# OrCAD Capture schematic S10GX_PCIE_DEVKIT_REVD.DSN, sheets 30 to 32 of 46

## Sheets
30 Max10 USB Blaster II: size C
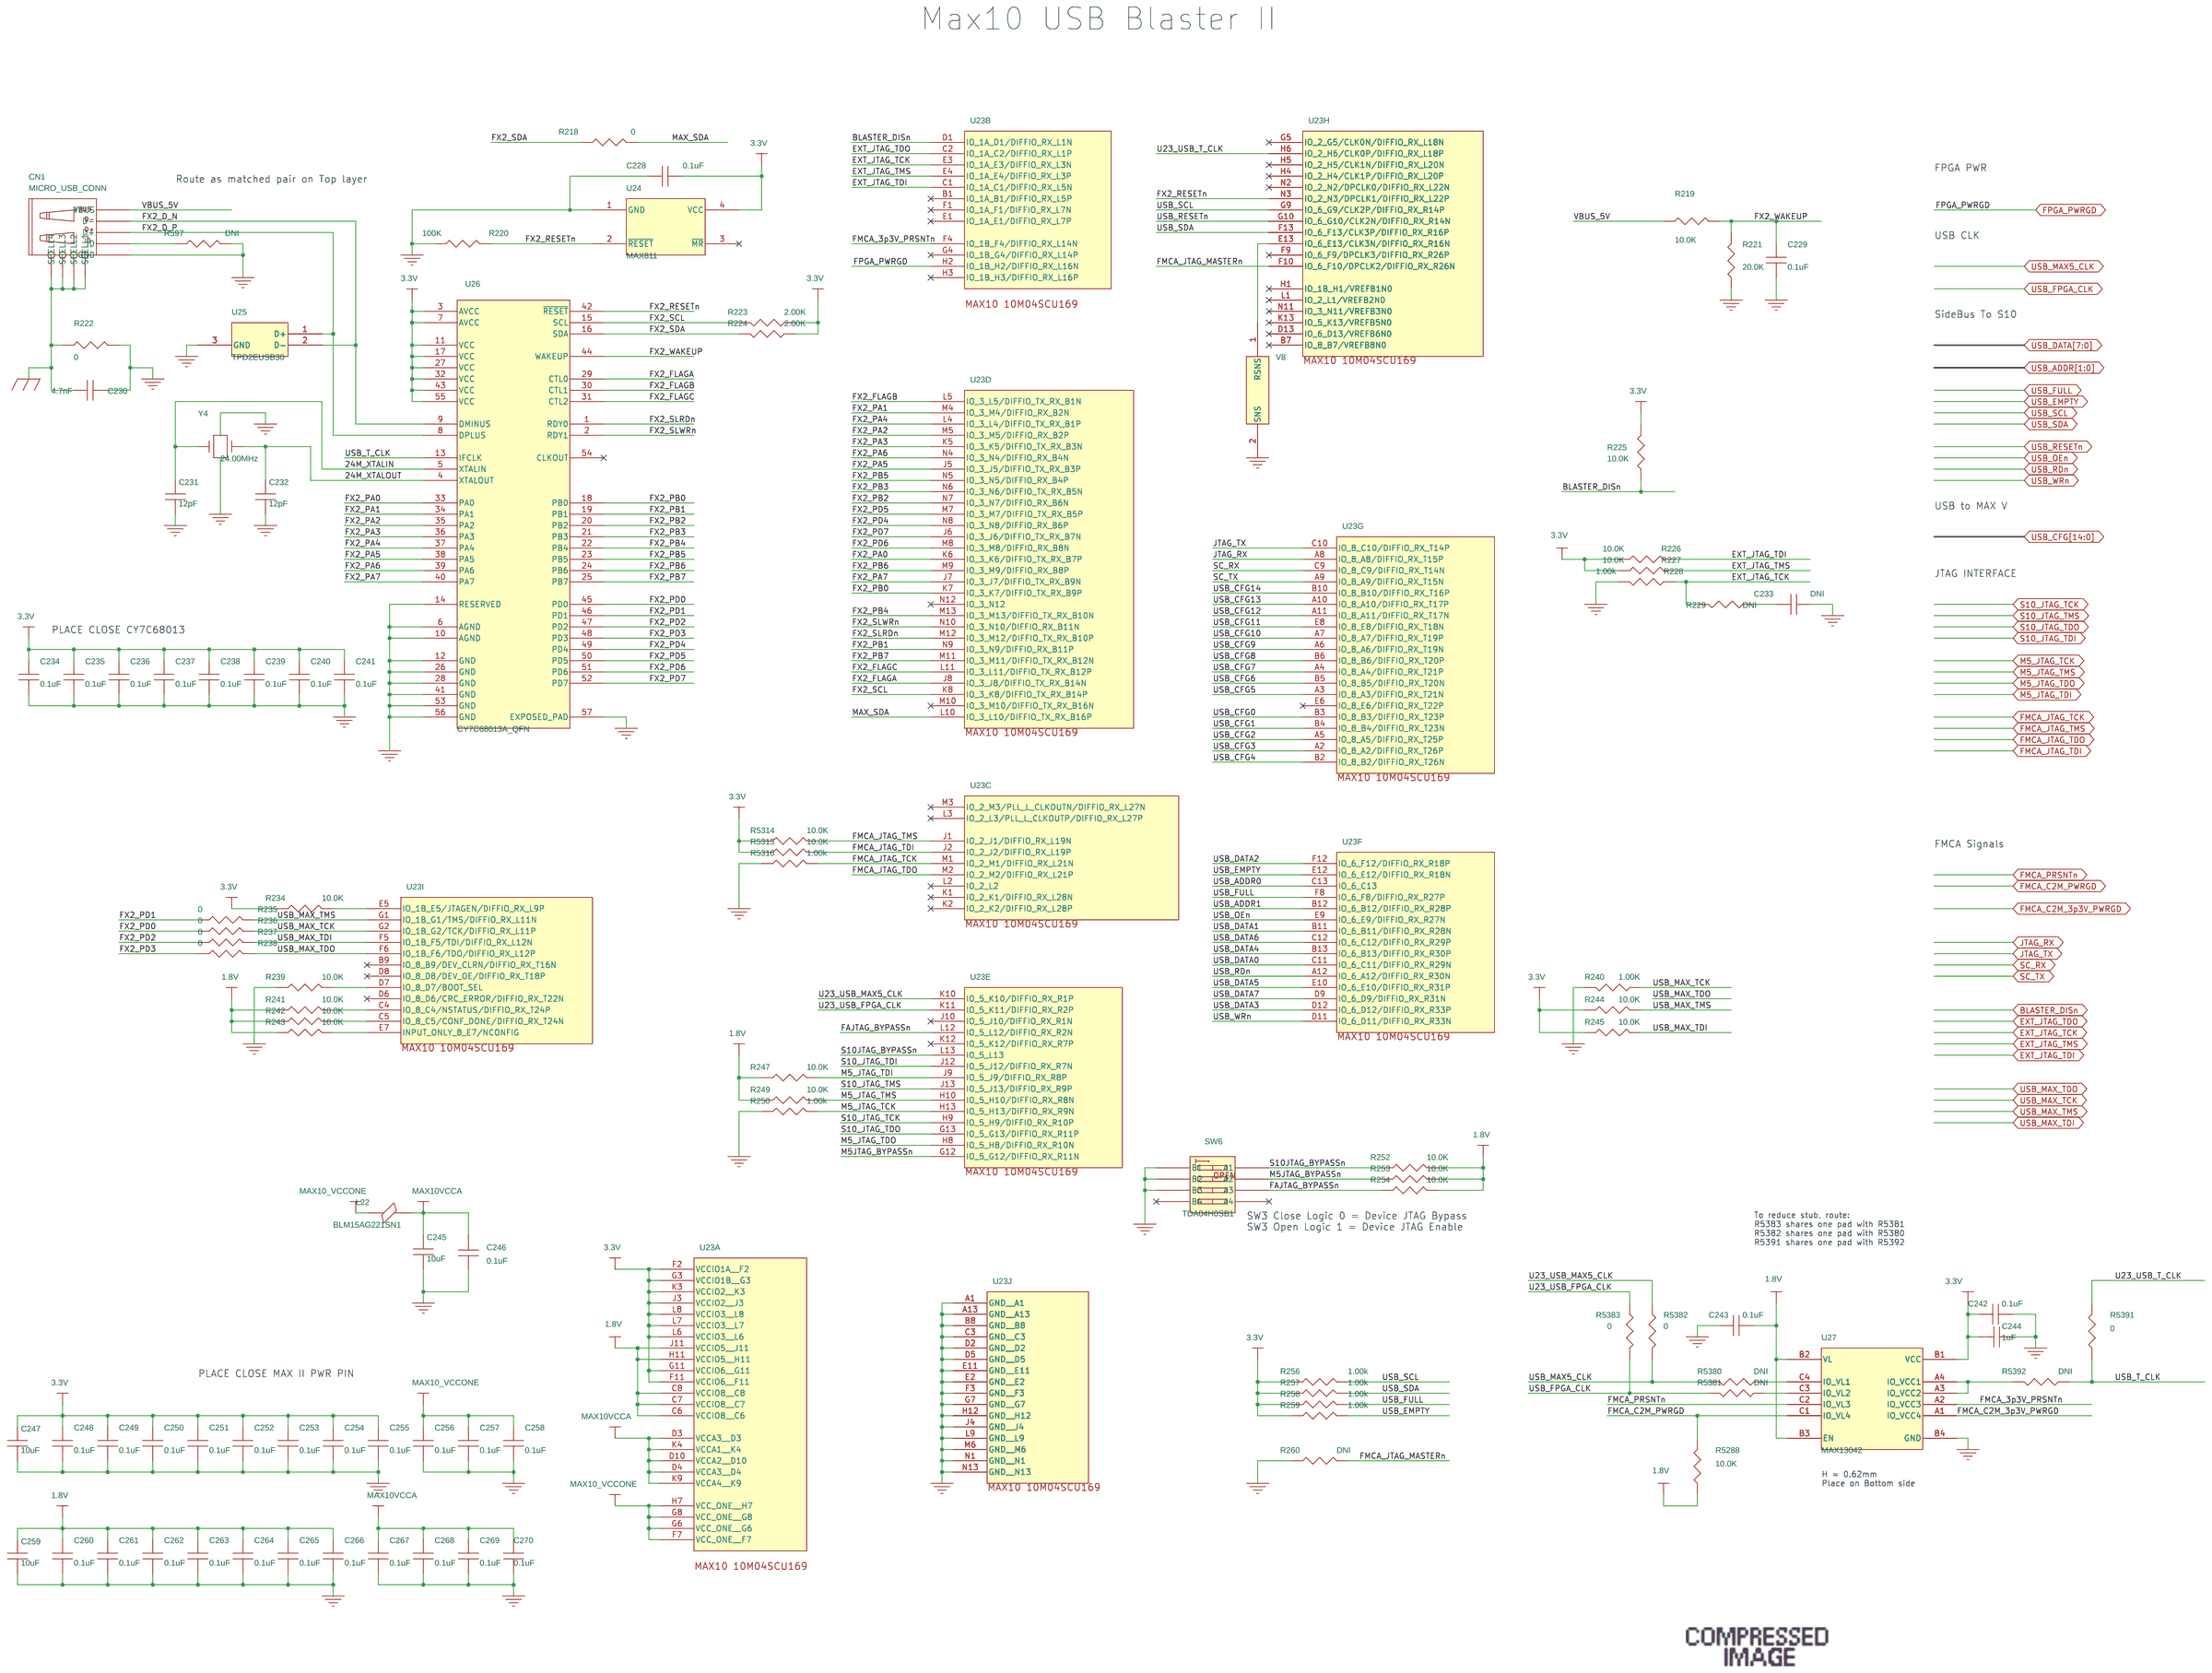
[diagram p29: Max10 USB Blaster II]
31 LT2987 Power Seq: size C
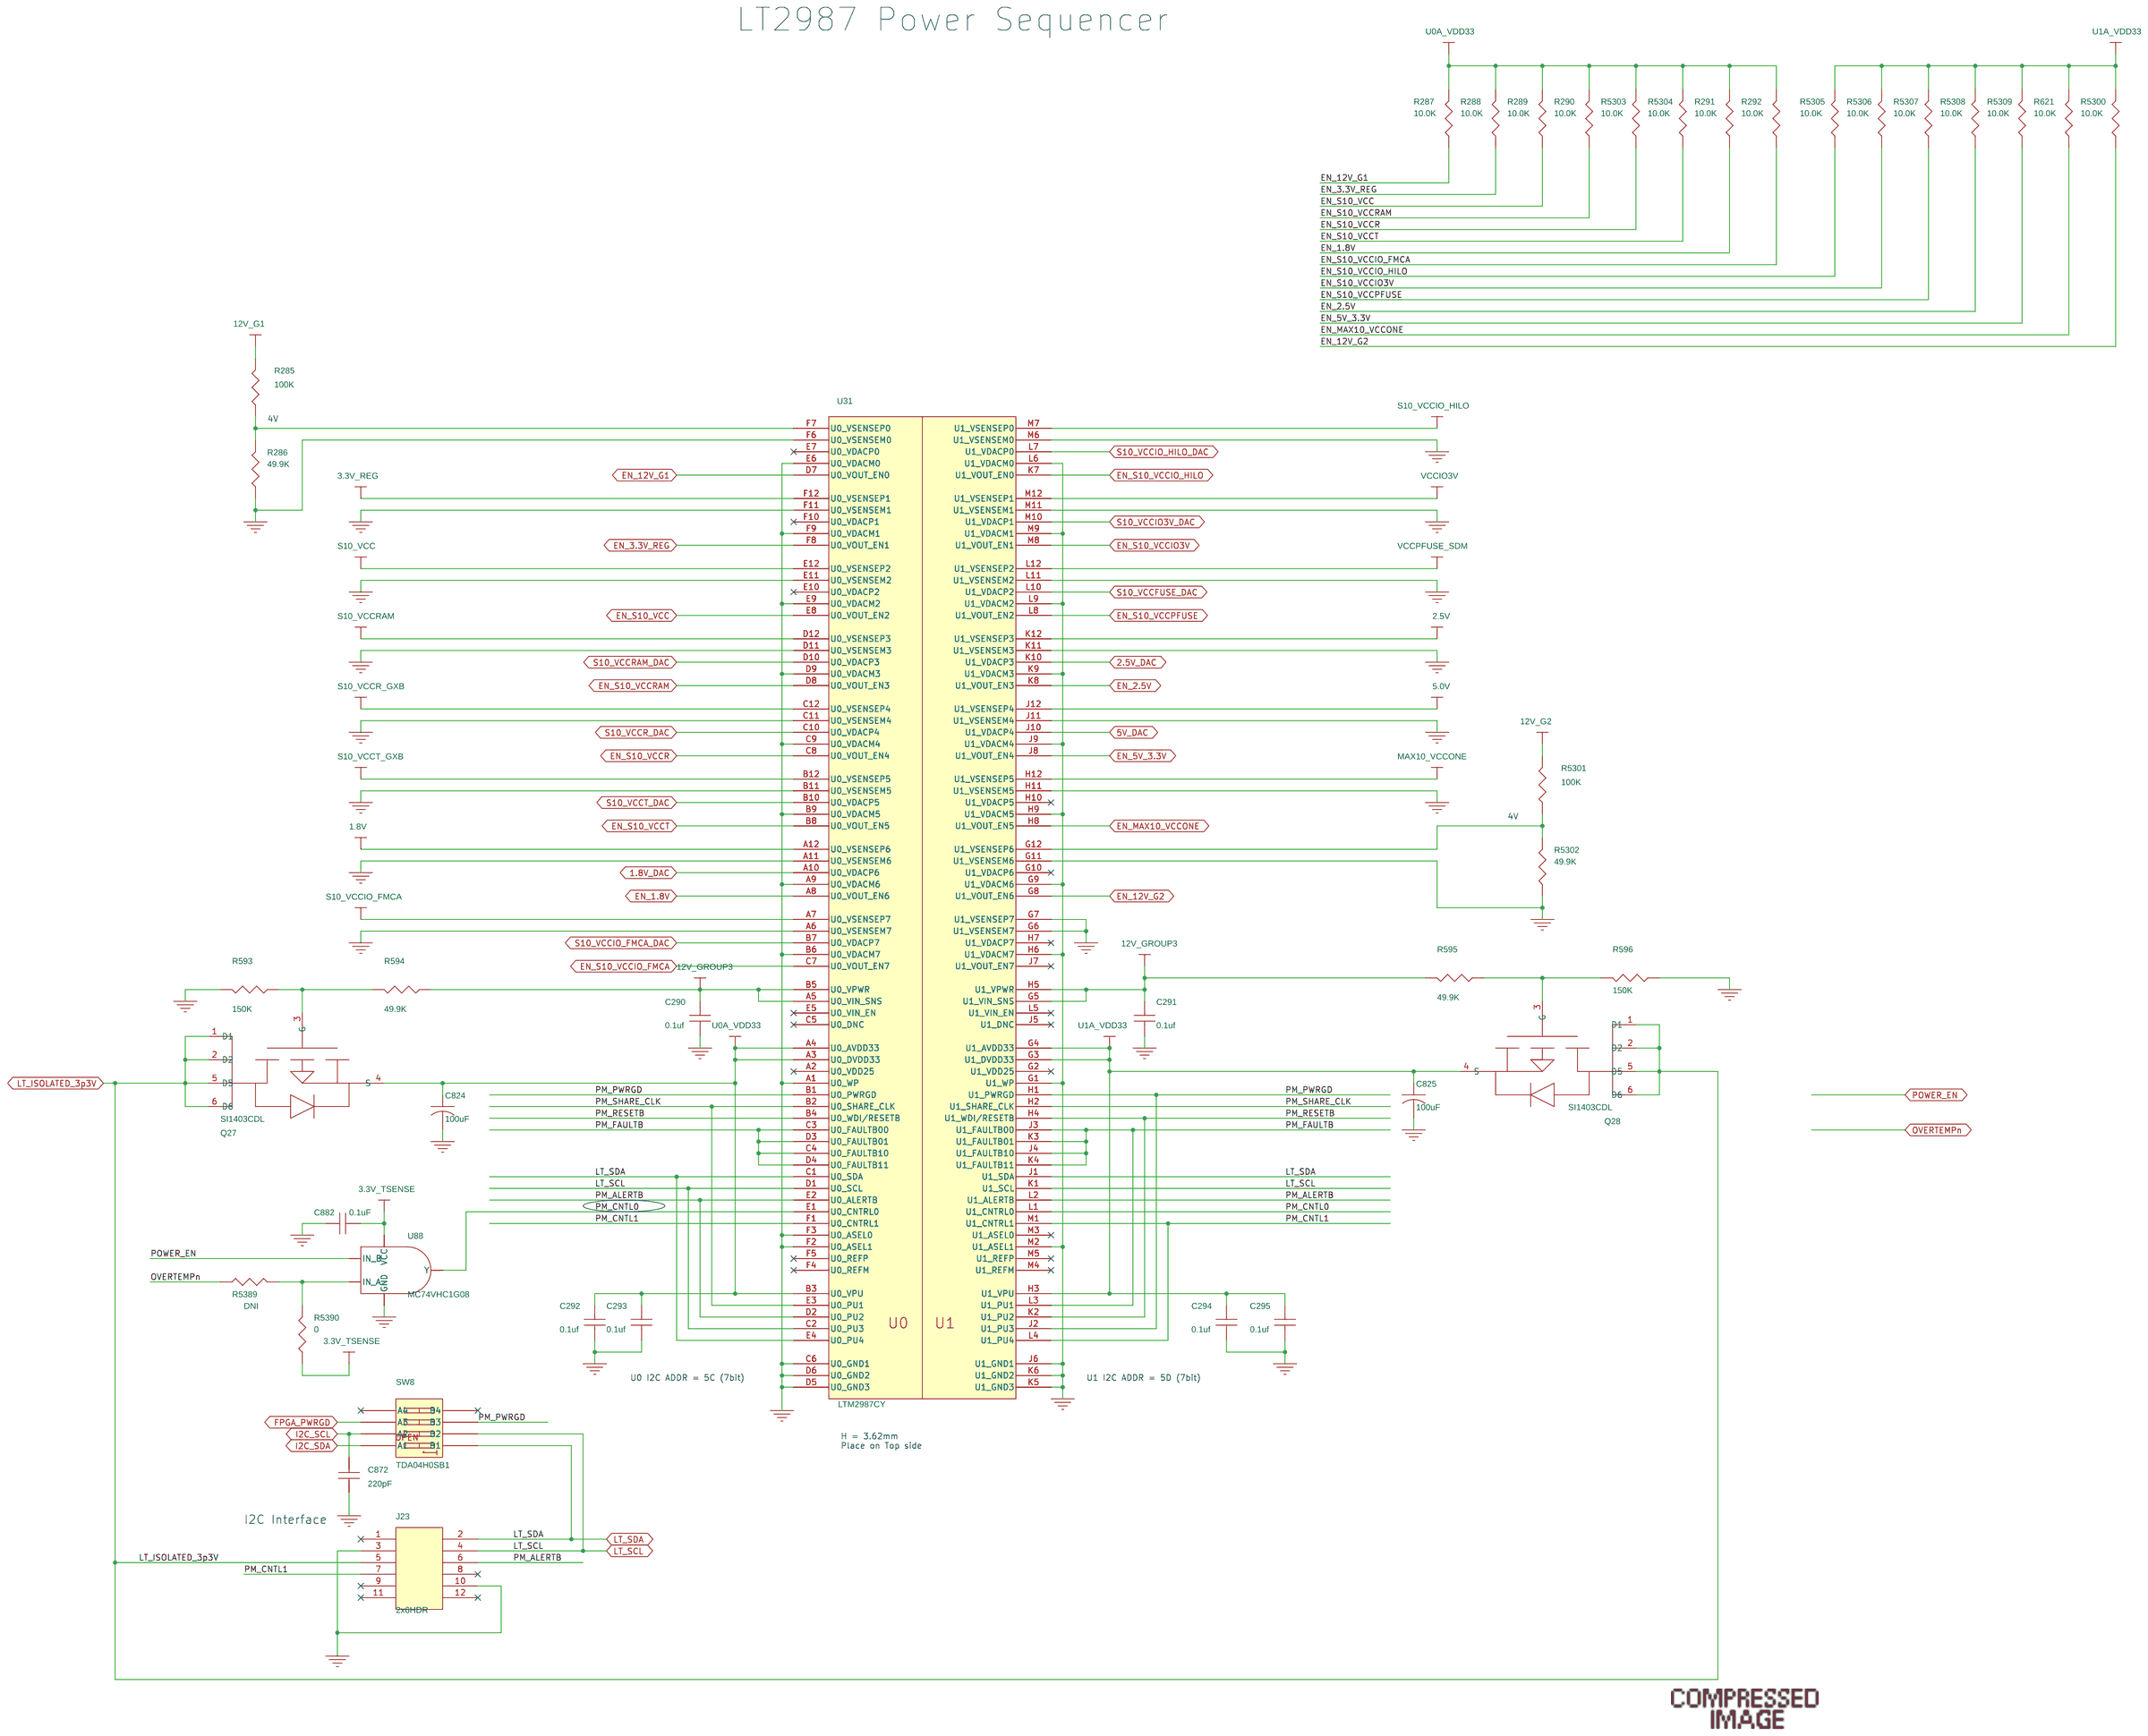
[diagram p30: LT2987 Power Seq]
32 Current & Temp Sense: size C
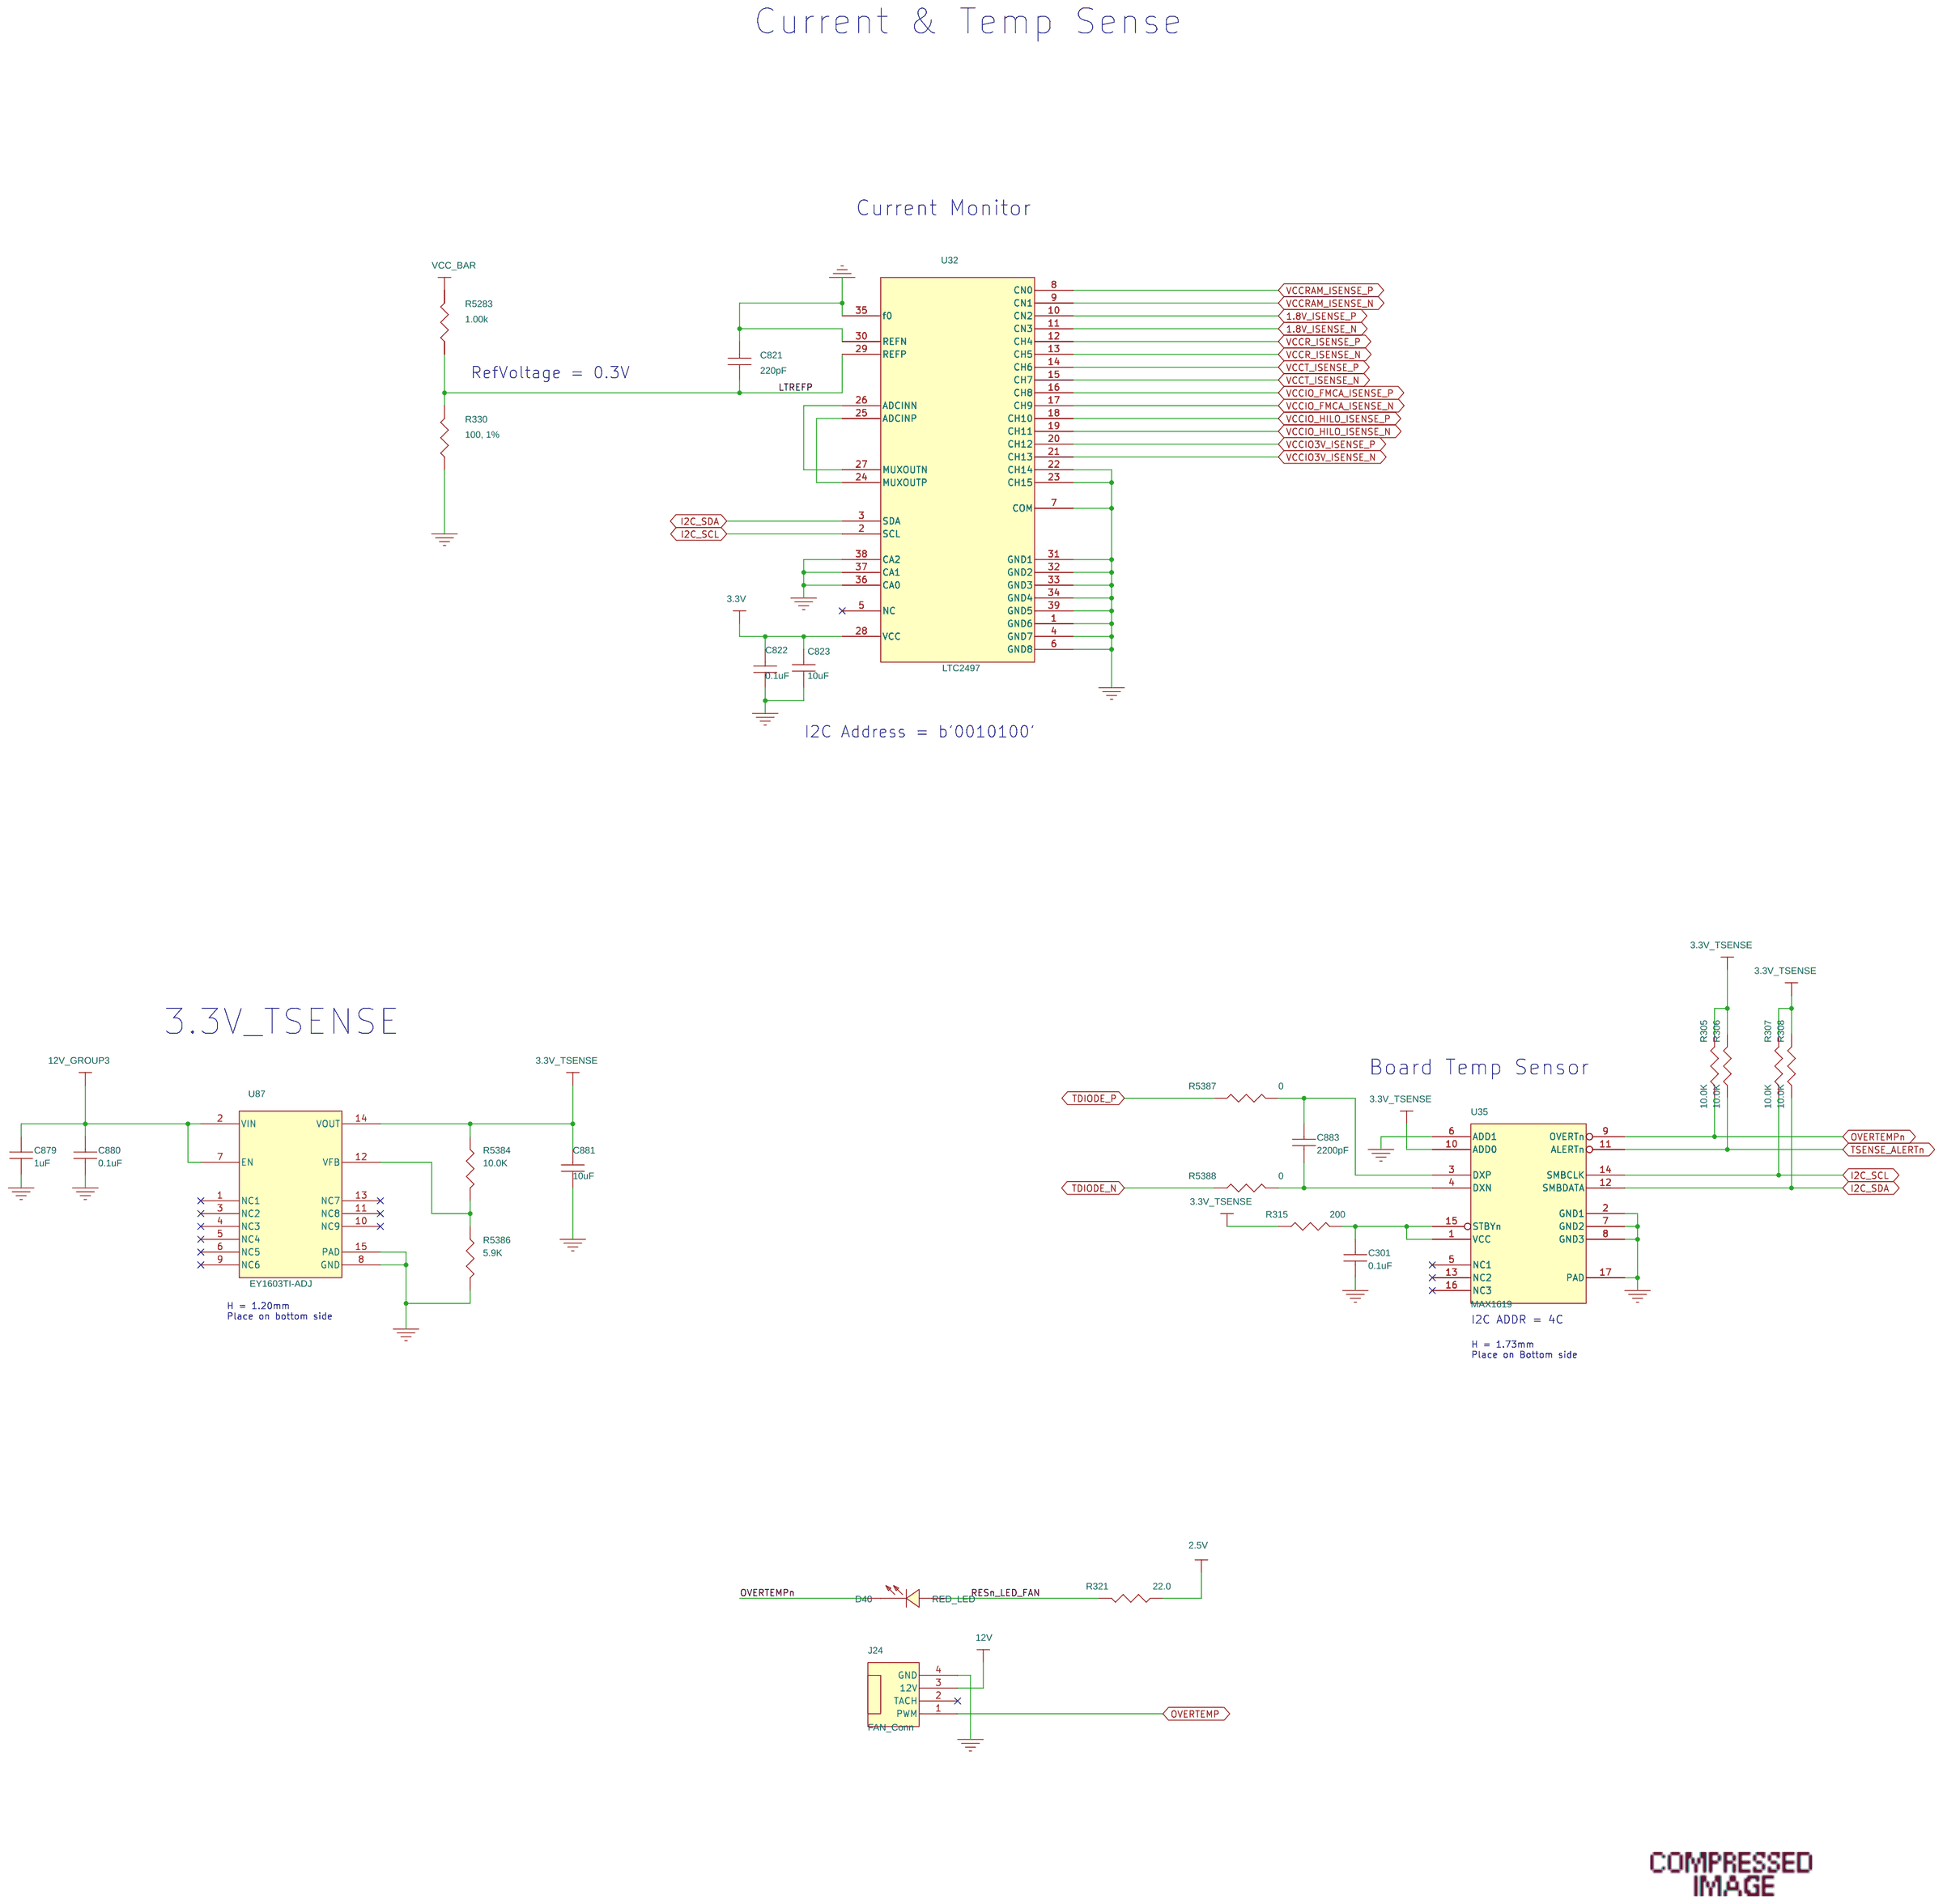
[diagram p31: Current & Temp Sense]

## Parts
sheet Current & Temp Sense
C301  0.1uF  [0402]
C821  220pF  [0402]
C822  0.1uF  [0402]
C823  10uF  [C0805]
C879  1uF  [0603]
C880  0.1uF  [0402]
C881  10uF  [0603]
C883  2200pF  [0402]
D40  RED_LED  [LED_0603]
J24  FAN_Conn  [Molex_0470533000]
R305  10.0K  [0402]
R306  10.0K  [0402]
R307  10.0K  [0402]
R308  10.0K  [0402]
R315  200  [0402]
R321  22.0  [0402]
R330  100, 1%  [0402]
R5283  1.00k  [0402]
R5384  10.0K  [0402]
R5386  5.9K  [0402]
R5387  0  [0402]
R5388  0  [0402]
U32  LTC2497  [LTQFN38]
U35  MAX1619  [QSOP16_EP]
U87  EY1603TI-ADJ  [HTSSOP-14]
sheet LT2987 Power Seq
C290  0.1uf  [0603]
C291  0.1uf  [0603]
C292  0.1uf  [0603]
C293  0.1uf  [0603]
C294  0.1uf  [0603]
C295  0.1uf  [0603]
C824  100uF  [Avx-1210_case-b]
C825  100uF  [Avx-1210_case-b]
C872  220pF  [0402]
C882  0.1uF  [0402]
J23  2x6HDR  [2X6HDR-2mmX2mm]
Q27  SI1403CDL  [SOT-363]
Q28  SI1403CDL  [SOT-363]
R285  100K  [0402]
R286  49.9K  [0402]
R287  10.0K  [0402]
R288  10.0K  [0402]
R289  10.0K  [0402]
R290  10.0K  [0402]
R291  10.0K  [0402]
R292  10.0K  [0402]
R593  150K  [0402]
R594  49.9K  [0402]
R595  49.9K  [0402]
R596  150K  [0402]
R621  10.0K  [0402]
R5300  10.0K  [0402]
R5301  100K  [0402]
R5302  49.9K  [0402]
R5303  10.0K  [0402]
R5304  10.0K  [0402]
R5305  10.0K  [0402]
R5306  10.0K  [0402]
R5307  10.0K  [0402]
R5308  10.0K  [0402]
R5309  10.0K  [0402]
R5389  DNI  [0402]
R5390  0  [0402]
SW8  TDA04H0SB1  [DIPSWITCH_SMT_QUAD]
U31  LTM2987CY  [BGA-144]
U88  MC74VHC1G08  [TSOP-5]
sheet Max10 USB Blaster II
C228  0.1uF  [0402]
C229  0.1uF  [0402]
C230  4.7nF  [0402]
C231  12pF  [0402]
C232  12pF  [0402]
C233  DNI  [0402]
C234  0.1uF  [0402]
C235  0.1uF  [0402]
C236  0.1uF  [0402]
C237  0.1uF  [0402]
C238  0.1uF  [0402]
C239  0.1uF  [0402]
C240  0.1uF  [0402]
C241  0.1uF  [0402]
C242  0.1uF  [0402]
C243  0.1uF  [0402]
C244  1uF  [0402]
C245  10uF  [0603]
C246  0.1uF  [0402]
C247  10uF  [0603]
C248  0.1uF  [0402]
C249  0.1uF  [0402]
C250  0.1uF  [0402]
C251  0.1uF  [0402]
C252  0.1uF  [0402]
C253  0.1uF  [0402]
C254  0.1uF  [0402]
C255  0.1uF  [0402]
C256  0.1uF  [0402]
C257  0.1uF  [0402]
C258  0.1uF  [0402]
C259  10uF  [0603]
C260  0.1uF  [0402]
C261  0.1uF  [0402]
C262  0.1uF  [0402]
C263  0.1uF  [0402]
C264  0.1uF  [0402]
C265  0.1uF  [0402]
C266  0.1uF  [0402]
C267  0.1uF  [0402]
C268  0.1uF  [0402]
C269  0.1uF  [0402]
C270  0.1uF  [0402]
CN1  MICRO_USB_CONN  [molex-micro-usb-47589-001]
L22  BLM15AG221SN1  [0402]
R218  0  [0402]
R219  10.0K  [0402]
R220  100K  [0402]
R221  20.0K  [0402]
R222  0  [0402]
R223  2.00K  [0402]
R224  2.00K  [0402]
R225  10.0K  [0402]
R226  10.0K  [0402]
R227  10.0K  [0402]
R228  1.00k  [0402]
R229  DNI  [0402]
R234  10.0K  [0402]
R235  0  [0402]
R236  0  [0402]
R237  0  [0402]
R238  0  [0402]
R239  10.0K  [0402]
R240  1.00K  [0402]
R241  10.0K  [0402]
R242  10.0K  [0402]
R243  10.0K  [0402]
R244  10.0K  [0402]
R245  10.0K  [0402]
R247  10.0K  [0402]
R249  10.0K  [0402]
R250  1.00k  [0402]
R252  10.0K  [0402]
R253  10.0K  [0402]
R254  10.0K  [0402]
R256  1.00k  [0402]
R257  1.00k  [0402]
R258  1.00k  [0402]
R259  1.00k  [0402]
R260  DNI  [0402]
R597  DNI  [0402]
R5288  10.0K  [0402]
R5314  10.0K  [0402]
R5315  10.0K  [0402]
R5316  1.00k  [0402]
R5380  DNI  [0402]
R5381  DNI  [0402]
R5382  0  [0402]
R5383  0  [0402]
R5391  0  [0402]
R5392  DNI  [0402]
SW6  TDA04H0SB1  [DIPSWITCH_SMT_QUAD]
U23  10M04SCU169  [BGA169-0R80-11X11]  (sections A,B,C,D,E,F,G,H,I,J)
U24  MAX811  [SOT-143]
U25  TPD2EUSB30  [DRT]
U26  CY7C68013A_QFN  [QFN56]
U27  MAX13042  [UCSP-12]
V8  SENSE_PAD  [SENSE]
Y4  24.00MHz  [XTAL_FA-128]

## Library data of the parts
C301 C880 C882 = CAP: CAP - CERAMIC,  0.1UF 0402 25VDC Y5V; AGILE_LINK: http://sj-agile9app/Agile/PLMServlet?action=OpenEmailObject&classid=10000&objid=213459527; Item Num: P03-15057R; LIFECYCLE_PHASE: Active; Lead Free Status: Lead Free; MFR_LIFECYCLE: Active; Manufacturer: Murata; Manufacturer Part Num: GRM155F51E104ZA01D; Num Pins: 2; PART_SUBCLASS: CAPACITORS; Part Class: CAPACITORS; RATED_VOLTAGE: 25V; RoHS Compliant: RoHS Compliant; TOLERANCE: +80%/-20%
C821 C872 = CAP: CAP - CERAMIC, 220PF, 10%, 50V, 0402, X7R; Dielectric: X5R; Item Num: P03-15090R; Lead Free Status: Yes; Manufacturer: Murata; Manufacturer Part Num: GRM155R71H221KA01D; Manufacturer's Part No.: GRM155R71H221KA01D; Num Pins: 2; Part Class: CAPACITORS; Price: 0.07; RoHS Compliant: Yes; Tolerance: 10%
C822 = CAP: CAP CER 0.1UF 25V 20% X7R 0402; Item Num: P03-17618R; LIFECYCLE_PHASE: Active; Lead Free Status: Lead Free; Manufacturer: Murata; Manufacturer Part Num: GRM155R71E104KE14D; Num Pins: 2; Part Class: CAPACITORS; Price: 0; RoHS Compliant: RoHS Compliant
C823 = CAP: SMD/SMT 10uF 10% 16Volts  0805; Item Num: P03-17702R; Lead Free Status: No; Manufacturer: TDK Electronics; Manufacturer Part Num: C2012X5R1C106K085AC; Manufacturer's Part No.: ECJ-2FB1A106K; Num Pins: 2; Part Class: CAPACITORS; RoHS Compliant: Yes
C879 = CAP: CAP - CER, 1UF, 25V, +/-10%, X5R, 0603 SMD; AGILE_LINK: http://sj-agile9app/Agile/PLMServlet?action=OpenEmailObject&classid=10000&objid=213459527; Item Num: P03-16324R; LIFECYCLE_PHASE: Active; Lead Free Status: Lead Free; MFR_LIFECYCLE: Active; Manufacturer: Murata; Manufacturer Part Num: GRM188R61E105KA12D; Num Pins: 2; PART_SUBCLASS: CAPACITORS; Part Class: CAPACITORS; RATED_VOLTAGE: 25V; RoHS Compliant: RoHS Compliant; TOLERANCE: +/-10%
C881 = CAP: CAP CER 10UF 25V 20% JB 0603; Item Num: P03-17784R; Lead Free Status: Yes; Manufacturer: TDK; Manufacturer Part Num: C1608JB1E106M080AC; Num Pins: 2; Part Class: Capacitors; Price: 0; RoHS Compliant: Yes
C883 = CAP: CCAP CER 2200PF 50V 10% X7R 0402; AGILE_LINK: http://sj-agile9app/Agile/PLMServlet?action=OpenEmailObject&classid=10000&objid=213459527; Item Num: P03-15048R; LIFECYCLE_PHASE: Active; Lead Free Status: Lead Free; MFR_LIFECYCLE: Active; Manufacturer: Murata; Manufacturer Part Num: GRM155R71H222KA01D; Num Pins: 2; PART_SUBCLASS: CAPACITORS; Part Class: CAPACITORS; RATED_VOLTAGE: 50V; RoHS Compliant: RoHS Compliant; TOLERANCE: +80%/-20%
D40 = LED_WURTH: LED -SUPER RED, VF=1.9V, IF=0.03A, 0603; Item Num: P09-21345R; LIFECYCLE_PHASE: Active; Lead Free Status: Lead Free; Manufacturer: Wurth Electroniks; Manufacturer Part Num: 150060SS75000; Num Pins: 2; PART_SUBCLASS: LEDS; Part Class: LEDS; RoHS Compliant: RoHS Compliant
J24 = FAN_Conn: 4 POSITIONS HEADER, UNSHROUDED CONNECTOR 0.100" (2.54MM) THROUGH HOLE TIN; Item Num: P23-38775R; Manufacturer Name: Molex; Manufacturer Part Num: 0470533000
R226 R227 R234 R239 R241-R245 R247 R249 R252-R254 R305-R308 R5288 R5314 R5315 = RESISTOR: RES,10.0K OHMS,1.0%,1/16W, 0402; AGILE_LINK: http://sj-agile9app/Agile/PLMServlet?action=OpenEmailObject&classid=10000&objid=146548997; Item Num: P02-11364R; LIFECYCLE_PHASE: Active; Lead Free Status: No; MFR_LIFECYCLE: Active; Manufacturer: Panasonic; Manufacturer Part Num: ERJ-2RKF1002X; Num Pins: 2; PART_SUBCLASS: RESISTORS; POWER: 1/16W; RoHS Compliant: Yes; TOLERANCE: +/-1%
R315 = RESISTOR: RES 200 OHM 1/16W 5% 0402 SMD; Item Num: P02-14026R; Manufacturer: Panasonic; Manufacturer Part Num: ERJ-2GEJ201X; Num Pins: 2; Part Class: RESISTORS; RoHS Compliant: Yes
R321 = RESISTOR: RES - 22.0 OHM, 1/16W, 1%, 0402 SMD; Item Num: P02-16269R; Lead Free Status: Yes; Manufacturer: Panasonic; Manufacturer Part Num: ERJ-2RKF22R0X; Num Pins: 2; Part Class: Resistors; Price: 0
R330 = RESISTOR: RES,100 OHMS,1.0%,1/16W,0402; Item Num: P02-11381R; Lead Free Status: No; Manufacturer: Panasonic; Manufacturer Part Num: ERJ-2RKF1000X; Num Pins: 2; Part Class: Resistors; Price: 0; RoHS Compliant: Yes; Tolerance: 1%
R228 R250 R256-R259 R5283 R5316 = RESISTOR: RES,1.00K OHMS,1.0%,1/16W,0402; Item Num: P02-11372R; Lead Free Status: No; Manufacturer: Panasonic; Manufacturer Part Num: ERJ-2RKF1001X; Num Pins: 2; Part Class: Resistors
R219 R287-R292 R621 R5300 R5303-R5309 R5384 = RESISTOR: RES,10.0K OHMS,1.0%,1/16W, 0402; AGILE_LINK: http://sj-agile9app/Agile/PLMServlet?action=OpenEmailObject&classid=10000&objid=146548997; Item Num: P02-11364R; LIFECYCLE_PHASE: Active; Lead Free Status: No; MFR_LIFECYCLE: Active; Manufacturer: Panasonic; Manufacturer Part Num: ERJ-2RKF1002X; Num Pins: 2; PART_SUBCLASS: RESISTORS; POWER: 1/16W; RESISTANCE: 10K; RoHS Compliant: Yes; TOLERANCE: +/-1%
R5386 = RESISTOR: RES - 5.9K OHM, 1/16W, 1%, 0402 SMD; AGILE_LINK: http://sj-agile9app/Agile/PLMServlet?action=OpenEmailObject&classid=10000&objid=146548997; Item Num: P02-15347R; LIFECYCLE_PHASE: Active; Lead Free Status: No; MFR_LIFECYCLE: Active; Manufacturer: Panasonic; Manufacturer Part Num: ERJ-2RKF5901x; Num Pins: 2; PART_SUBCLASS: RESISTORS; POWER: 1/16W; RoHS Compliant: Yes; TOLERANCE: +/-1%
R218 R222 R235-R238 R5382 R5383 R5387 R5388 R5390 R5391 = RESISTOR: RES ZERO OHM 1/16W 5% 0402 SMD; Altera Part No.: P02-14020R; Item Num: P02-14020R; Lead Free Status: No; Manufacturer: Panasonic; Manufacturer Part Num: ERJ-2GE0R00X; Num Pins: 2; Part Class: RESISTORS; RoHS Compliant: Yes; Tolerance: 5%
U32 = LTC2497
U35 = MAX1619_0: IC, Temperature Sensor, SMBus Interface, QSOP-16; AGILE_LINK: http://sj-agile9app/Agile/PLMServlet?action=OpenEmailObject&classid=10000&objid=188479272; Item Num: P01-13019R; LIFECYCLE_PHASE: Active; Lead Free Status: Lead Free; MFR_LIFECYCLE: Active; Manufacturer: Maxim Integrated Products, Inc.; Manufacturer Part Num: MAX1619MEE+T; Num Pins: 16; PART_SUBCLASS: ICS; Price: 3.5; RoHS Compliant: RoHS Compliant
U87 = EY1603TI-ADJ: IC - EY1603 40V, LOW QUIESCENT CURRENT, 150MA LINEAR REGULATOR; Item Num: P01-18060R; Manufacturer: Altera
C290-C295 = CAP: CAP - 0.1UF 0603 16V X7R; AGILE_LINK: http://sj-agile9app/Agile/PLMServlet?action=OpenEmailObject&classid=10000&objid=14603414; CAPACITANCE: 0.1uF; Item Num: P03-08618R; LIFECYCLE_PHASE: Active; MFR_LIFECYCLE: Active; Manufacturer: Murata; Manufacturer Part Num: GRM188R71C104KA01D; Num Pins: 2; PART_SUBCLASS: CAPACITORS; Price: 0.154; RATED_VOLTAGE: 16V; RoHS Compliant: RoHS Compliant; Supplier Part Num: PCC1762TR-ND
C824 C825 = PCAP: CAP - TANT, 100UF, 6.3V, 20%, ESR 0.045 OHM, POLY SMD; AGILE_LINK: http://sj-agile9app/Agile/PLMServlet?action=OpenEmailObject&classid=10000&objid=257237054; Item Num: P03-17352R; LIFECYCLE_PHASE: Active; Lead Free Status: Lead Free; MFR_LIFECYCLE: Active; Manufacturer: AVX Corp; Manufacturer Part Num: TCJB107M006R0045; Num Pins: 2; PART_SUBCLASS: CAPACITORS; RATED_VOLTAGE: 6.3V; RoHS Compliant: RoHS Compliant; TOLERANCE: +/-20%
J23 = 2X6HDR: CONN HEADER 12POS 2MM SMT DL PCB; Item Num: P23-38256R; Manufacturer Part Num: 98424-G52-12LF
Q27 Q28 = SI1403DL: MOSFET P-CH 20V 1.6A SOT-363; Item Num: P18-31470R; Manufacturer: Vishay Siliconix; Manufacturer Part Num: SI1403CDL-T1-GE3
R220 R285 R5301 = RESISTOR: RES,100K OHMS,1.0%,1/16W,0402; Item Num: P02-11386R; Lead Free Status: No; Manufacturer: Panasonic; Manufacturer Part Num: ERJ-2RKF1003X; Num Pins: 2; Part Class: Resistors; Price: 0; RoHS Compliant: Yes
R286 R594 R595 R5302 = RESISTOR: RES 49.9K OHM 1/16W 1% 0402 SMD; Item Num: P02-15867R; Lead Free Status: Yes; Manufacturer: Panasonic; Manufacturer Part Num: ERJ-2RKF4992X; Num Pins: 2; Part Class: Resistors; Price: 0
R593 R596 = RESISTOR: RES - 150K OHMS, 1.0%, 1/16W, 0402; Item Num: P02-15627R; Lead Free Status: Yes; Manufacturer: Panasonic; Manufacturer Part Num: ERJ-2RKF1503x; Num Pins: 2; Part Class: Resistors; Price: 0
R597 R5389 = RESISTOR: RES ZERO OHM 1/16W 5% 0402 SMD; Altera Part No.: P02-14020R; Item Num: P02-14020R; Lead Free Status: No; Manufacturer: Panasonic; Manufacturer Part Num: ERJ-2GE0R00X; Num Pins: 2; Part Class: RESISTORS; Price: 0; RoHS Compliant: Yes; Tolerance: 5%
SW8 = SPST4: SWITCHES - 4 POS, 8 PIN, Ultra-mini SMT Half-pitch Slider DIP Switch; AGILE_LINK: http://sj-agile9app/Agile/PLMServlet?action=OpenEmailObject&classid=10000&objid=258073635; Item Num: P11-24098R; LIFECYCLE_PHASE: Preliminary; Lead Free Status: Not Lead Free; MFR_LIFECYCLE: Active; Manufacturer: C & K Components/ITT Industries; Num Pins: 8; PART_SUBCLASS: SWITCHES; RoHS Compliant: RoHS Compliant
U31 = LT2987CY_0: IC 16-CHL UMODULE PMBUS PWR SYS MANAGER LTM2987; Item Num: P01-18011R; Manufacturer: Linear Technology; Manufacturer Part Num: LTM2987CY#PBF; Manufacturer Part Number: LTM2987CY#PBF
U88 = Single_2-input_AND-Gate: IC GATE AND SGL CMOS 2IN 5TSOP; Item Num: P01-17902R; Manufacturer: On-Semi; Manufacturer Part Num: MC74VHC1G08DTT1G
C228 C229 C234-C241 C248-C258 C260-C270 = CAP: CAP - CERAMIC,  0.1UF 0402 25VDC Y5V; Dielectric: Y5V; Item Num: P03-15057R; LIFECYCLE_PHASE: Active; Lead Free Status: Lead Free; MFR_LIFECYCLE: Active; Manufacturer: Murata; Manufacturer Part Num: GRM155F51E104ZA01D; Num Pins: 2; PART_SUBCLASS: CAPACITORS; Part Class: CAPACITORS; RATED_VOLTAGE: 25V; RoHS Compliant: RoHS Compliant; TOLERANCE: +80%/-20%
C230 = CAP: CAP - CER 4700PF 50V 10% X7R 0402; AGILE_LINK: http://sj-agile9app/Agile/PLMServlet?action=OpenEmailObject&classid=10000&objid=215384813; Item Num: P03-15074R; LIFECYCLE_PHASE: Active; Lead Free Status: Lead Free; MFR_LIFECYCLE: Active; Manufacturer: Murata; Manufacturer Part Num: GRM155R71H472KA01D; Num Pins: 2; PACKAGING: Tape & Reel (TR); PART_SUBCLASS: CAPACITORS; RATED_VOLTAGE: 50V; RoHS Compliant: RoHS Compliant; Supplier Part Num: GRM155R71H472KA01D; Tolerance: +/-10%
C231 C232 = CAP: CAP - 12PF, 50V, +/-5%, CERAMIC, 0402 SMD; AGILE_LINK: http://sj-agile9app/Agile/PLMServlet?action=OpenEmailObject&classid=10000&objid=257385742; Item Num: P03-15352R; LIFECYCLE_PHASE: Active; Lead Free Status: Lead Free; MFR_LIFECYCLE: Active; Manufacturer: Murata; Manufacturer Part Num: GRM1555C1H120JA01D; Num Pins: 2; PART_SUBCLASS: CAPACITORS; RATED_VOLTAGE: 50V; RoHS Compliant: RoHS Compliant; TOLERANCE: +/-5%
C233 = CAP: CAP DNI 0402; LIFECYCLE_PHASE: Active; Lead Free Status: Lead Free; Num Pins: 2; Part Class: CAPACITORS; Price: 0
C242 C243 C246 = CAP_NP: CAP, CERAMIC, 0.1UF, 0402, 10%, 10VDC,  X5R; AGILE_LINK: http://sj-agile9app/Agile/PLMServlet?action=OpenEmailObject&classid=10000&objid=188516424; Item Num: P03-15030R; LIFECYCLE_PHASE: Active; MFR_LIFECYCLE: Active; Manufacturer: Murata; Manufacturer Part Num: GRM155R61A104KA01D; Num Pins: 2; PART_SUBCLASS: CAPACITORS; RATED_VOLTAGE: 10V; RoHS Compliant: RoHS Compliant; TOLERANCE: +/-10%
C244 = CAP: CAP - CER, 1uF, 10V, +/-10%, X5R, 0402; Item Num: P03-15479R; Lead Free Status: Yes; Manufacturer: Murata; Manufacturer Part Num: GRM155R61A105KE15D; Num Pins: 2; Part Class: CAPACITORS; RoHS Compliant: Yes
C245 C247 C259 = CAP: CAP - CER, 10UF, 6.3V, +/-20%, X5R, 0603 SMD; AGILE_LINK: http://sj-agile9app/Agile/PLMServlet?action=OpenEmailObject&classid=10000&objid=260383822; Item Num: P03-16323R; LIFECYCLE_PHASE: Active; Lead Free Status: Lead Free; MFR_LIFECYCLE: Active; Manufacturer: Murata; Manufacturer Part Num: GRM188R60J106ME47D; Num Pins: 2; PART_SUBCLASS: CAPACITORS; RATED_VOLTAGE: 6.3V; RoHS Compliant: RoHS Compliant; TOLERANCE: +/-20%
CN1 = MICRO_USB_CONN: RECEPTACLE, USB 3.0, MICRO B, R/A; Item Num: P23-38552R; Lead Free Status: Yes; MFR_LIFECYCLE: Active; Manufacturer: Molex; Manufacturer Part Num: 47589-0001; Num Pins: 9; Part Class: Connectors; RoHS Compliant: Yes
L22 = BEAD_FERRITE_SM: IND - SMD EMI FILTERS/CHIP FERRITE BEAD, 220-OHM @ 100MHZ, 0.35-OHM DCR, 0402; Item Num: P04-16225R; LIFECYCLE_PHASE: Active; MFR_LIFECYCLE: Active; Manufacturer: Murata; Manufacturer Part Num: BLM15AG221SN1x; Num Pins: 2; PART_SUBCLASS: INDUCTORS
R221 = RESISTOR: RES 20.0K OHM 1/16W 1% 0402 SMD; Item Num: P02-14071R; Lead Free Status: Yes; Manufacturer: Panasonic; Manufacturer Part Num: ERJ-2RKF2002X; Num Pins: 2; Part Class: RESISTORS; RoHS Compliant: Yes
R223 R224 = RESISTOR: RES,2.00K OHMS,1.0%,1/16W,0402; Item Num: P02-11376R; Lead Free Status: No; Manufacturer: Panasonic; Manufacturer Part Num: ERJ-2RKF2001X; Manufacturer's Part No.: ERJ-2RKF2001X; Num Pins: 2; Part Class: RESISTORS; Price: 0; RoHS Compliant: Yes
R225 = R: RES,10.0K OHMS,1.0%,1/16W, 0402; Item Num: P02-11364R; Lead Free Status: No; Manufacturer: Panasonic; Manufacturer Part Num: ERJ-2RKF1002X; Num Pins: 2; Part Class: Resistors; Price: 0; RoHS Compliant: Yes
R229 = R: RES DNI 0402; Lead Free Status: No; Num Pins: 2; Part Class: Resistors; Price: 0; RoHS Compliant: Yes
R240 = RESISTOR: RES,1.00K OHMS,1.0%,1/16W,0402; Item Num: P02-11372R; Lead Free Status: No; Manufacturer: Panasonic; Manufacturer Part Num: ERJ-2RKF1001X; Num Pins: 2; Part Class: Resistors; Price: 0
R260 = RESISTOR: RES,10.0K OHMS,1.0%,1/16W, 0402; AGILE_LINK: http://sj-agile9app/Agile/PLMServlet?action=OpenEmailObject&classid=10000&objid=146548997; Item Num: P02-11364R; LIFECYCLE_PHASE: Active; Lead Free Status: No; MFR_LIFECYCLE: Active; Manufacturer: Panasonic; Manufacturer Part Num: ERJ-2RKF1002X; Num Pins: 2; PART_SUBCLASS: RESISTORS; POWER: 1/16W; RESISTANCE: 10.0K; RoHS Compliant: Yes; TOLERANCE: +/-1%
R5380 R5381 R5392 = RESISTOR: RES - 20 OHM, 1/10W, 5%, 0402 SMD; Item Num: P02-17594R; Lead Free Status: Yes; Manufacturer: Panasonic; Manufacturer Part Num: ERJ-2GEJ200X; Num Pins: 2; Part Class: Resistors; Price: 0
SW6 = SPST4: SWITCHES - 4 POS, 8 PIN, Ultra-mini SMT Half-pitch Slider DIP Switch; AGILE_LINK: http://sj-agile9app/Agile/PLMServlet?action=OpenEmailObject&classid=10000&objid=258073635; Item Num: P11-24098R; LIFECYCLE_PHASE: Preliminary; Lead Free Status: Not Lead Free; MFR_LIFECYCLE: Active; Manufacturer: C & K Components/ITT Industries; Num Pins: 8; PART_SUBCLASS: SWITCHES; RoHS Compliant: Yes
U23 = 10M04SCU169
U24 = MAX811: IC - MPU V-MONITOR 2.93V, RESET/POWER-ON RESET, SOT143-4; Item Num: P01-17588R; Lead Free Status: Yes; Manufacturer: Maxim Integrated Products; Manufacturer Part Num: MAX811SEUS+T; Num Pins: 4; Part Class: ICs; RoHS Compliant: Yes
U25 = TPD2EUSB30: DIODE - FULL SPEED USB ESD SOLUTION, 2CH, SOT3; Item Num: P08-20777R; Lead Free Status: Yes; MFR_LIFECYCLE: Active; Manufacturer: Texas Instruments; Manufacturer Part Num: TPD2EUSB30DRxx; Num Pins: 3; Part Class: ICS; RoHS Compliant: Yes
U26 = CY7C68013A_56QFN: IC - EZ-USB FX2LP Microcontroller 400KHz, 56-QFN, 3.3V; Item Num: P01-17739R; Lead Free Status: Yes; Manufacturer: Cypress; Manufacturer Part Num: CY7C68013A-56LTXCx; Num Pins: 57; Part Class: ICs; RoHS Compliant: Yes
U27 = MAX13042_0: IC - HIGH SPEED LEVEL TRANSLATOR, 1.62V-3.6V, 100MBPS, 1.54MM X 2.12MM 12UCSP; Item Num: P01-17606R; Lead Free Status: Yes; Manufacturer: Maxim Integrated Products; Manufacturer Part Num: MAX13042EEBC+T
V8 = SENSE_PAD: Item Num: P23-SENSE; Manufacturer: NONE; Manufacturer Part Num: NONE
Y4 = CRYSTAL_SM_13: CRYSTAL - MINI XTL, 24.00 MHZ, +/-50PPM, +/-30PPM-20~75C, 12PF, 2.0mm x 1.6mm SMD; Item Num: P07-19648R; Lead Free Status: Yes; MFR_LIFECYCLE: Active; Manufacturer: Epson Toyocom; Manufacturer Part Num: FA-128 24.0000MB-W:; Num Pins: 4; RoHS Compliant: Yes

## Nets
1.8V: C243.2 C259.1 C260.1 C261.1 C262.1 C263.1 C264.1 C265.1 C266.1 R241.1 R242.1 R243.1 R247.1 R249.1 R252.2 R253.2 R254.2 R5288.1 U23.C6(VCCIO8_) U23.C7(VCCIO8_) U23.C8(VCCIO8_) U23.H11(VCCIO5_) U23.J11(VCCIO5_) U27.B2(VL) U27.B3(EN) U31.A12(U0_VSENSEP6) ; also on sheet 6 9 15 16 17 19 20 24 27 28 29 39 45
1.8V_DAC: U31.A10(U0_VDACP6) ; also on sheet 39
1.8V_ISENSE_N: U32.11(CN3) ; also on sheet 39
1.8V_ISENSE_P: U32.10(CN2) ; also on sheet 39
2.5V: R321.2 U31.K12(U1_VSENSEP3) ; also on sheet 18 19 21 23 28 29 43 46
2.5V_DAC: U31.K10(U1_VDACP3) ; also on sheet 43
3.3V: C228.2 C234.1 C235.1 C236.1 C237.1 C238.1 C239.1 C240.1 C241.1 C242.1 C244.2 C247.1 C248.1 C249.1 C250.1 C251.1 C252.1 C253.1 C254.1 C255.1 C822.2 C823.1 R223.2 R224.2 R225.2 R226.2 R227.2 R234.1 R244.2 R245.2 R256.1 R257.1 R258.1 R259.1 R5283.2 R5314.1 R5315.1 U23.F2(VCCIO1A_) U23.F11(VCCIO6_) U23.G3(VCCIO1B_) U23.G11(VCCIO6_) U23.J3(VCCIO2_) U23.K3(VCCIO2_) U23.L6(VCCIO3_) U23.L7(VCCIO3_) U23.L8(VCCIO3_) U24.4(VCC) U26.3(AVCC) U26.7(AVCC) U26.11(VCC) U26.17(VCC) U26.27(VCC) U26.32(VCC) U26.43(VCC) U26.55(VCC) U27.B1(VCC) U32.28(VCC) ; also on sheet 9 17 18 19 23 24 25 27 28 29 34
3.3V_REG: U31.F12(U0_VSENSEP1) ; also on sheet 34 41 42 43 44
3.3V_TSENSE: C881.1 C882.2 R305.2 R306.2 R307.2 R308.2 R315.1 R5384.1 R5390.2 U35.10(ADD0) U87.14(VOUT) U88.5(VCC) ; also on sheet 19
5.0V: U31.J12(U1_VSENSEP4) ; also on sheet 33 36 43 46
5V_DAC: U31.J10(U1_VDACP4) ; also on sheet 43
12V: J24.3(12V) ; also on sheet 25 29 33
12V_G1: R285.2 ; also on sheet 33 35 36 37 38
12V_G2: R5301.2 ; also on sheet 33 39 40 43
12V_GROUP3: C290.1 C291.1 C879.1 C880.1 R594.1 R595.2 U31.A5(U0_VIN_SNS) U31.B5(U0_VPWR) U31.G5(U1_VIN_SNS) U31.H5(U1_VPWR) U87.2(VIN) U87.7(EN) ; also on sheet 33 34 46
GND: C228.1 C229.2 C230.2 C231.2 C232.2 C233.1 C234.2 C235.2 C236.2 C237.2 C238.2 C239.2 C240.2 C241.2 C242.2 C243.1 C244.1 C245.2 C246.1 C247.2 C248.2 C249.2 C250.2 C251.2 C252.2 C253.2 C254.2 C255.2 C256.2 C257.2 C258.2 C259.2 C260.2 C261.2 C262.2 C263.2 C264.2 C265.2 C266.2 C267.2 C268.2 C269.2 C270.2 C290.2 C291.2 C292.2 C293.2 C294.2 C295.2 C301.2 C821.2 C822.1 C823.2 C824.2 C825.2 C872.1 C879.2 C880.2 C881.2 C882.1 CN1.5(GND) J23.3 J23.10 J24.4(GND) R220.2 R221.1 R222.2 R228.1 R239.1 R240.2 R250.1 R260.1 R286.1 R330.1 R593.2 R596.1 R597.2 R5302.1 R5316.1 R5386.2 SW6.6(B3) SW6.7(B2) SW6.8(B1) U23.A1(GND_) U23.A13(GND_) U23.B8(GND_) U23.C3(GND_) U23.D2(GND_) U23.D5(GND_) U23.E2(GND_) U23.E11(GND_) U23.F3(GND_) U23.G7(GND_) U23.H12(GND_) U23.J4(GND_) U23.L9(GND_) U23.M6(GND_) U23.N1(GND_) U23.N13(GND_) U24.1(GND) U25.3(GND) U26.6(AGND) U26.10(AGND) U26.12(GND) U26.14(RESERVED) U26.26(GND) U26.28(GND) U26.41(GND) U26.53(GND) U26.56(GND) U26.57(EXPOSED_PAD) U27.B4(GND) U31.A1(U0_WP) U31.A6(U0_VSENSEM7) U31.A9(U0_VDACM6) U31.A11(U0_VSENSEM6) U31.B6(U0_VDACM7) U31.B9(U0_VDACM5) U31.B11(U0_VSENSEM5) U31.C6(U0_GND1) U31.C9(U0_VDACM4) U31.C11(U0_VSENSEM4) U31.D5(U0_GND3) U31.D6(U0_GND2) U31.D9(U0_VDACM3) U31.D11(U0_VSENSEM3) U31.E6(U0_VDACM0) U31.E9(U0_VDACM2) U31.E11(U0_VSENSEM2) U31.F2(U0_ASEL1) U31.F3(U0_ASEL0) U31.F6(U0_VSENSEM0) U31.F9(U0_VDACM1) U31.F11(U0_VSENSEM1) U31.G1(U1_WP) U31.G6(U1_VSENSEM7) U31.G7(U1_VSENSEP7) U31.G9(U1_VDACM6) U31.G11(U1_VSENSEM6) U31.H6(U1_VDACM7) U31.H9(U1_VDACM5) U31.H11(U1_VSENSEM5) U31.J6(U1_GND1) U31.J9(U1_VDACM4) U31.J11(U1_VSENSEM4) U31.K5(U1_GND3) U31.K6(U1_GND2) U31.K9(U1_VDACM3) U31.K11(U1_VSENSEM3) U31.L6(U1_VDACM0) U31.L9(U1_VDACM2) U31.L11(U1_VSENSEM2) U31.M2(U1_ASEL1) U31.M6(U1_VSENSEM0) U31.M9(U1_VDACM1) U31.M11(U1_VSENSEM1) U32.1(GND6) U32.4(GND7) U32.6(GND8) U32.7(COM) U32.22(CH14) U32.23(CH15) U32.30(REFN) U32.31(GND1) U32.32(GND2) U32.33(GND3) U32.34(GND4) U32.35(f0) U32.36(CA0) U32.37(CA1) U32.38(CA2) U32.39(GND5) U35.2(GND1) U35.6(ADD1) U35.7(GND2) U35.8(GND3) U35.17(PAD) U87.8(GND) U87.15(PAD) U88.3(GND) V8.2(SNS) Y4.2 Y4.4 ; also on sheet 6 7 8 9 10 11 12 13 14 15 16 17 18 19 20 21 23 24 25 27 28 29 33 34 35 36 37 38 39 40 41 42 43 44 45 46
GND_EARTH: C230.1 CN1.6(SHELL1) CN1.7(SHELL2) CN1.8(SHELL3) CN1.9(SHELL4) R222.1
VBUS_5V: CN1.1(VBUS) R219.1
VCCIO3V: U31.M12(U1_VSENSEP1) ; also on sheet 6 15 44 45 46
VCCIO3V_ISENSE_N: U32.21(CH13) ; also on sheet 44
VCCIO3V_ISENSE_P: U32.20(CH12) ; also on sheet 44
VCCIO_FMCA_ISENSE_N: U32.17(CH9) ; also on sheet 41
VCCIO_FMCA_ISENSE_P: U32.16(CH8) ; also on sheet 41
VCCIO_HILO_ISENSE_N: U32.19(CH11) ; also on sheet 42
VCCIO_HILO_ISENSE_P: U32.18(CH10) ; also on sheet 42
VCCPFUSE_SDM: U31.L12(U1_VSENSEP2) ; also on sheet 15 43 46
VCCR_ISENSE_N: U32.13(CH5) ; also on sheet 40
VCCR_ISENSE_P: U32.12(CH4) ; also on sheet 40
VCCRAM_ISENSE_N: U32.9(CN1) ; also on sheet 38
VCCRAM_ISENSE_P: U32.8(CN0) ; also on sheet 38
VCCT_ISENSE_N: U32.15(CH7) ; also on sheet 40
VCCT_ISENSE_P: U32.14(CH6) ; also on sheet 40
24M_XTALIN: C231.1 U26.5(XTALIN) Y4.1
24M_XTALOUT: C232.1 U26.4(XTALOUT) Y4.3
BLASTER_DISn: R225.1 U23.D1(IO_1A_D1/DIFFIO_RX_L1N) ; also on sheet 29
EN_1.8V: R291.1 U31.A8(U0_VOUT_EN6) ; also on sheet 39 46
EN_2.5V: R5308.1 U31.K8(U1_VOUT_EN3) ; also on sheet 43 46
EN_3.3V_REG: R288.1 U31.F8(U0_VOUT_EN1) ; also on sheet 34
EN_5V_3.3V: R5309.1 U31.J8(U1_VOUT_EN4) ; also on sheet 34 43 46
EN_12V_G1: R287.1 U31.D7(U0_VOUT_EN0) ; also on sheet 33
EN_12V_G2: R5300.1 U31.G8(U1_VOUT_EN6) ; also on sheet 33
EN_MAX10_VCCONE: R621.1 U31.H8(U1_VOUT_EN5) ; also on sheet 34
EN_S10_VCC: R289.1 U31.E8(U0_VOUT_EN2) ; also on sheet 35
EN_S10_VCCIO3V: R5306.1 U31.M8(U1_VOUT_EN1) ; also on sheet 44 46
EN_S10_VCCIO_FMCA: R292.1 U31.C7(U0_VOUT_EN7) ; also on sheet 33 41 46
EN_S10_VCCIO_HILO: R5305.1 U31.K7(U1_VOUT_EN0) ; also on sheet 42 46
EN_S10_VCCPFUSE: R5307.1 U31.L8(U1_VOUT_EN2) ; also on sheet 43 46
EN_S10_VCCR: R5303.1 U31.C8(U0_VOUT_EN4) ; also on sheet 40 46
EN_S10_VCCRAM: R290.1 U31.D8(U0_VOUT_EN3) ; also on sheet 38 46
EN_S10_VCCT: R5304.1 U31.B8(U0_VOUT_EN5) ; also on sheet 40 46
EXT_JTAG_TCK: R228.2 R229.2 U23.E3(IO_1A_E3/DIFFIO_RX_L3N) ; also on sheet 29
EXT_JTAG_TDI: R226.1 U23.C1(IO_1A_C1/DIFFIO_RX_L5N) ; also on sheet 29
EXT_JTAG_TDO: U23.C2(IO_1A_C2/DIFFIO_RX_L1P) ; also on sheet 29
EXT_JTAG_TMS: R227.1 U23.E4(IO_1A_E4/DIFFIO_RX_L3P) ; also on sheet 29
FAJTAG_BYPASSn: R254.1 SW6.3(A3) U23.L12(IO_5_L12/DIFFIO_RX_R2N)
FMCA_3p3V_PRSNTn: U23.F4(IO_1B_F4/DIFFIO_RX_L14N) U27.A2(IO_VCC3)
FMCA_C2M_3p3V_PWRGD: U27.A1(IO_VCC4) ; also on sheet 25
FMCA_C2M_PWRGD: R5288.2 U27.C1(IO_VL4) ; also on sheet 19
FMCA_JTAG_MASTERn: R260.2 U23.F10(IO_6_F10/DPCLK2/DIFFIO_RX_R26N)
FMCA_JTAG_TCK: R5316.2 U23.M1(IO_2_M1/DIFFIO_RX_L21N) ; also on sheet 25
FMCA_JTAG_TDI: R5315.2 U23.J2(IO_2_J2/DIFFIO_RX_L19P) ; also on sheet 25
FMCA_JTAG_TDO: U23.M2(IO_2_M2/DIFFIO_RX_L21P) ; also on sheet 25
FMCA_JTAG_TMS: R5314.2 U23.J1(IO_2_J1/DIFFIO_RX_L19N) ; also on sheet 25
FMCA_PRSNTn: U27.C2(IO_VL3) ; also on sheet 10 19 25 29
FPGA_PWRGD: SW8.3(A3) U23.H2(IO_1B_H2/DIFFIO_RX_L16N)
FX2_D_N: CN1.2(D-) U25.2(D-) U26.9(DMINUS)
FX2_D_P: CN1.3(D+) U25.1(D+) U26.8(DPLUS)
FX2_FLAGA: U23.J8(IO_3_J8/DIFFIO_TX_RX_B14N) U26.29(CTL0)
FX2_FLAGB: U23.L5(IO_3_L5/DIFFIO_TX_RX_B1N) U26.30(CTL1)
FX2_FLAGC: U23.L11(IO_3_L11/DIFFIO_TX_RX_B12P) U26.31(CTL2)
FX2_PA0: U23.K6(IO_3_K6/DIFFIO_TX_RX_B7P) U26.33(PA0)
FX2_PA1: U23.M4(IO_3_M4/DIFFIO_RX_B2N) U26.34(PA1)
FX2_PA2: U23.M5(IO_3_M5/DIFFIO_RX_B2P) U26.35(PA2)
FX2_PA3: U23.K5(IO_3_K5/DIFFIO_TX_RX_B3N) U26.36(PA3)
FX2_PA4: U23.L4(IO_3_L4/DIFFIO_TX_RX_B1P) U26.37(PA4)
FX2_PA5: U23.J5(IO_3_J5/DIFFIO_TX_RX_B3P) U26.38(PA5)
FX2_PA6: U23.N4(IO_3_N4/DIFFIO_RX_B4N) U26.39(PA6)
FX2_PA7: U23.J7(IO_3_J7/DIFFIO_TX_RX_B9N) U26.40(PA7)
FX2_PB0: U23.K7(IO_3_K7/DIFFIO_TX_RX_B9P) U26.18(PB0)
FX2_PB1: U23.N9(IO_3_N9/DIFFIO_RX_B11P) U26.19(PB1)
FX2_PB2: U23.N7(IO_3_N7/DIFFIO_RX_B6N) U26.20(PB2)
FX2_PB3: U23.N6(IO_3_N6/DIFFIO_TX_RX_B5N) U26.21(PB3)
FX2_PB4: U23.M13(IO_3_M13/DIFFIO_TX_RX_B10N) U26.22(PB4)
FX2_PB5: U23.N5(IO_3_N5/DIFFIO_RX_B4P) U26.23(PB5)
FX2_PB6: U23.M9(IO_3_M9/DIFFIO_RX_B8P) U26.24(PB6)
FX2_PB7: U23.M11(IO_3_M11/DIFFIO_TX_RX_B12N) U26.25(PB7)
FX2_PD0: R236.2 U26.45(PD0)
FX2_PD1: R235.2 U26.46(PD1)
FX2_PD2: R237.2 U26.47(PD2)
FX2_PD3: R238.2 U26.48(PD3)
FX2_PD4: U23.N8(IO_3_N8/DIFFIO_RX_B6P) U26.49(PD4)
FX2_PD5: U23.M7(IO_3_M7/DIFFIO_TX_RX_B5P) U26.50(PD5)
FX2_PD6: U23.M8(IO_3_M8/DIFFIO_RX_B8N) U26.51(PD6)
FX2_PD7: U23.J6(IO_3_J6/DIFFIO_TX_RX_B7N) U26.52(PD7)
FX2_RESETn: R220.1 U23.N3(IO_2_N3/DPCLK1/DIFFIO_RX_L22P) U24.2(~{RESET}) U26.42(~{RESET})
FX2_SCL: R223.1 U23.K8(IO_3_K8/DIFFIO_TX_RX_B14P) U26.15(SCL)
FX2_SDA: R218.1 R224.1 U26.16(SDA)
FX2_SLRDn: U23.M12(IO_3_M12/DIFFIO_TX_RX_B10P) U26.1(RDY0)
FX2_SLWRn: U23.N10(IO_3_N10/DIFFIO_RX_B11N) U26.2(RDY1)
FX2_WAKEUP: C229.1 R219.2 R221.2 U26.44(WAKEUP)
I2C_SCL: C872.2 R307.1 SW8.2(A2) U32.2(SCL) U35.14(SMBCLK) ; also on sheet 18 19 29
I2C_SDA: R308.1 SW8.1(A1) U32.3(SDA) U35.12(SMBDATA) ; also on sheet 18 19 29
JTAG_RX: U23.A8(IO_8_A8/DIFFIO_RX_T15P) ; also on sheet 29
JTAG_TX: U23.C10(IO_8_C10/DIFFIO_RX_T14P) ; also on sheet 29
LT_ISOLATED_3p3V: J23.5 Q27.1(D1) Q27.2(D2) Q27.5(D5) Q27.6(D6) Q28.1(D1) Q28.2(D2) Q28.5(D5) Q28.6(D6) ; also on sheet 35
LT_SCL: J23.4 SW8.7(B2) U31.C2(U0_PU3) U31.D1(U0_SCL) U31.K1(U1_SCL) ; also on sheet 6 35
LT_SDA: J23.2 SW8.8(B1) U31.C1(U0_SDA) U31.E4(U0_PU4) U31.J1(U1_SDA) ; also on sheet 6 35
LTREFP: C821.1 R330.2 R5283.1 U32.29(REFP)
M5_JTAG_TCK: R250.2 U23.H13(IO_5_H13/DIFFIO_RX_R9N) ; also on sheet 19
M5_JTAG_TDI: R247.2 U23.J9(IO_5_J9/DIFFIO_RX_R8P) ; also on sheet 19
M5_JTAG_TDO: U23.H8(IO_5_H8/DIFFIO_RX_R10N) ; also on sheet 19
M5_JTAG_TMS: R249.2 U23.H10(IO_5_H10/DIFFIO_RX_R8N) ; also on sheet 19
M5JTAG_BYPASSn: R253.1 SW6.2(A2) U23.G12(IO_5_G12/DIFFIO_RX_R11N)
MAX10_VCCONE: C256.1 C257.1 C258.1 L22.1 U23.F7(VCC_ONE_) U23.G6(VCC_ONE_) U23.G8(VCC_ONE_) U23.H7(VCC_ONE_) U31.H12(U1_VSENSEP5) ; also on sheet 34
MAX10VCCA: C245.1 C246.2 C267.1 C268.1 C269.1 C270.1 L22.2 U23.D3(VCCA3_) U23.D4(VCCA3_) U23.D10(VCCA2_) U23.K4(VCCA1_) U23.K9(VCCA4_)
MAX_SDA: R218.2 U23.L10(IO_3_L10/DIFFIO_TX_RX_B16P)
OVERTEMP: J24.1(PWM) ; also on sheet 19
OVERTEMPn: D40.C(CATHODE) R305.1 R5389.2 U35.9(OVERTn) ; also on sheet 19
PM_ALERTB: J23.6 U31.D2(U0_PU2) U31.E2(U0_ALERTB) U31.L2(U1_ALERTB)
PM_CNTL0: U31.E1(U0_CNTRL0) U31.L1(U1_CNTRL0) U88.4(Y)
PM_CNTL1: J23.7 U31.F1(U0_CNTRL1) U31.L4(U1_PU4) U31.M1(U1_CNTRL1)
PM_FAULTB: U31.C3(U0_FAULTB00) U31.C4(U0_FAULTB10) U31.D3(U0_FAULTB01) U31.D4(U0_FAULTB11) U31.J3(U1_FAULTB00) U31.J4(U1_FAULTB10) U31.K3(U1_FAULTB01) U31.K4(U1_FAULTB11) U31.L3(U1_PU1)
PM_PWRGD: SW8.6(B3) U31.B1(U0_PWRGD) U31.H1(U1_PWRGD) U31.J2(U1_PU3)
PM_RESETB: U31.B4(U0_WDI/RESETB) U31.H4(U1_WDI/RESETB) U31.K2(U1_PU2)
PM_SHARE_CLK: U31.B2(U0_SHARE_CLK) U31.E3(U0_PU1) U31.H2(U1_SHARE_CLK)
POWER_EN: U88.1(IN_B) ; also on sheet 33
RESn_LED_FAN: D40.A(ANODE) R321.1
S10_JTAG_TCK: U23.H9(IO_5_H9/DIFFIO_RX_R10P) ; also on sheet 6
S10_JTAG_TDI: U23.J12(IO_5_J12/DIFFIO_RX_R7N) ; also on sheet 6
S10_JTAG_TDO: U23.G13(IO_5_G13/DIFFIO_RX_R11P) ; also on sheet 6
S10_JTAG_TMS: U23.J13(IO_5_J13/DIFFIO_RX_R9P) ; also on sheet 6
S10_VCC: U31.E12(U0_VSENSEP2) ; also on sheet 15 16 35 36 37 45
S10_VCCFUSE_DAC: U31.L10(U1_VDACP2) ; also on sheet 43
S10_VCCIO3V_DAC: U31.M10(U1_VDACP1) ; also on sheet 44
S10_VCCIO_FMCA: U31.A7(U0_VSENSEP7) ; also on sheet 9 15 25 41 45
S10_VCCIO_FMCA_DAC: U31.B7(U0_VDACP7) ; also on sheet 41
S10_VCCIO_HILO: U31.M7(U1_VSENSEP0) ; also on sheet 15 42 45
S10_VCCIO_HILO_DAC: U31.L7(U1_VDACP0) ; also on sheet 42
S10_VCCR_DAC: U31.C10(U0_VDACP4) ; also on sheet 40
S10_VCCR_GXB: U31.C12(U0_VSENSEP4) ; also on sheet 15 40 45
S10_VCCRAM: U31.D12(U0_VSENSEP3) ; also on sheet 15 38 45
S10_VCCRAM_DAC: U31.D10(U0_VDACP3) ; also on sheet 38
S10_VCCT_DAC: U31.B10(U0_VDACP5) ; also on sheet 40
S10_VCCT_GXB: U31.B12(U0_VSENSEP5) ; also on sheet 15 40 45
S10JTAG_BYPASSn: R252.1 SW6.1(A1) U23.L13(IO_5)
SC_RX: U23.C9(IO_8_C9/DIFFIO_RX_T14N) ; also on sheet 29
SC_TX: U23.A9(IO_8_A9/DIFFIO_RX_T15N) ; also on sheet 29
TDIODE_N: R5388.2 ; also on sheet 15
TDIODE_P: R5387.2 ; also on sheet 15
TSENSE_ALERTn: R306.1 U35.11(ALERTn) ; also on sheet 19
U0A_VDD33: C292.1 C293.1 C824.1 Q27.4(S) R287.2 R288.2 R289.2 R290.2 R291.2 R292.2 R5303.2 R5304.2 U31.A3(U0_DVDD33) U31.A4(U0_AVDD33) U31.B3(U0_VPU) ; also on sheet 6
U1A_VDD33: C294.1 C295.1 C825.1 Q28.4(S) R621.2 R5300.2 R5305.2 R5306.2 R5307.2 R5308.2 R5309.2 U31.G3(U1_DVDD33) U31.G4(U1_AVDD33) U31.H3(U1_VPU)
U23_USB_FPGA_CLK: R5383.2 U23.K11(IO_5_K11/DIFFIO_RX_R2P)
U23_USB_MAX5_CLK: R5382.2 U23.K10(IO_5_K10/DIFFIO_RX_R1P)
U23_USB_T_CLK: R5391.1 U23.H6(IO_2_H6/CLK0P/DIFFIO_RX_L18P)
USB_ADDR0: U23.C13(IO_6) ; also on sheet 6
USB_ADDR1: U23.B12(IO_6_B12/DIFFIO_RX_R28P) ; also on sheet 6
USB_CFG0: U23.B3(IO_8_B3/DIFFIO_RX_T23P) ; also on sheet 19
USB_CFG1: U23.B4(IO_8_B4/DIFFIO_RX_T23N) ; also on sheet 19
USB_CFG2: U23.A5(IO_8_A5/DIFFIO_RX_T25P) ; also on sheet 19
USB_CFG3: U23.A2(IO_8_A2/DIFFIO_RX_T26P) ; also on sheet 19
USB_CFG4: U23.B2(IO_8_B2/DIFFIO_RX_T26N) ; also on sheet 19
USB_CFG5: U23.A3(IO_8_A3/DIFFIO_RX_T21N) ; also on sheet 19
USB_CFG6: U23.B5(IO_8_B5/DIFFIO_RX_T20N) ; also on sheet 19
USB_CFG7: U23.A4(IO_8_A4/DIFFIO_RX_T21P) ; also on sheet 19
USB_CFG8: U23.B6(IO_8_B6/DIFFIO_RX_T20P) ; also on sheet 19
USB_CFG9: U23.A6(IO_8_A6/DIFFIO_RX_T19N) ; also on sheet 19
USB_CFG10: U23.A7(IO_8_A7/DIFFIO_RX_T19P) ; also on sheet 19
USB_CFG11: U23.E8(IO_8_E8/DIFFIO_RX_T18N) ; also on sheet 19
USB_CFG12: U23.A11(IO_8_A11/DIFFIO_RX_T17N) ; also on sheet 19
USB_CFG13: U23.A10(IO_8_A10/DIFFIO_RX_T17P) ; also on sheet 19
USB_CFG14: U23.B10(IO_8_B10/DIFFIO_RX_T16P) ; also on sheet 19
USB_DATA0: U23.C11(IO_6_C11/DIFFIO_RX_R29N) ; also on sheet 6
USB_DATA1: U23.B11(IO_6_B11/DIFFIO_RX_R28N) ; also on sheet 6
USB_DATA2: U23.F12(IO_6_F12/DIFFIO_RX_R18P) ; also on sheet 6
USB_DATA3: U23.D12(IO_6_D12/DIFFIO_RX_R33P) ; also on sheet 6
USB_DATA4: U23.B13(IO_6_B13/DIFFIO_RX_R30P) ; also on sheet 6
USB_DATA5: U23.E10(IO_6_E10/DIFFIO_RX_R31P) ; also on sheet 6
USB_DATA6: U23.C12(IO_6_C12/DIFFIO_RX_R29P) ; also on sheet 6
USB_DATA7: U23.D9(IO_6_D9/DIFFIO_RX_R31N) ; also on sheet 6
USB_EMPTY: R259.2 U23.E12(IO_6_E12/DIFFIO_RX_R18N) ; also on sheet 6
USB_FPGA_CLK: R5381.2 R5383.1 ; also on sheet 7
USB_FULL: R258.2 U23.F8(IO_6_F8/DIFFIO_RX_R27P) ; also on sheet 6
USB_MAX5_CLK: R5380.2 R5382.1 ; also on sheet 19
USB_MAX_TCK: R236.1 R240.1 U23.G2(IO_1B_G2/TCK/DIFFIO_RX_L11P) ; also on sheet 29
USB_MAX_TDI: R237.1 R245.1 U23.F5(IO_1B_F5/TDI/DIFFIO_RX_L12N) ; also on sheet 29
USB_MAX_TDO: R238.1 U23.F6(IO_1B_F6/TDO/DIFFIO_RX_L12P) ; also on sheet 29
USB_MAX_TMS: R235.1 R244.1 U23.G1(IO_1B_G1/TMS/DIFFIO_RX_L11N) ; also on sheet 29
USB_OEn: U23.E9(IO_6_E9/DIFFIO_RX_R27N) ; also on sheet 6
USB_RDn: U23.A12(IO_6_A12/DIFFIO_RX_R30N) ; also on sheet 6
USB_RESETn: U23.G10(IO_6_G10/CLK2N/DIFFIO_RX_R14N) ; also on sheet 6
USB_SCL: R256.2 U23.G9(IO_6_G9/CLK2P/DIFFIO_RX_R14P) ; also on sheet 6
USB_SDA: R257.2 U23.F13(IO_6_F13/CLK3P/DIFFIO_RX_R16P) ; also on sheet 6
USB_T_CLK: R5391.2 R5392.1 U26.13(IFCLK)
USB_WRn: U23.D11(IO_6_D11/DIFFIO_RX_R33N) ; also on sheet 6
N17212217: C301.1 R315.2 U35.1(VCC) U35.15(STBYn)
N18201550: R239.2 U23.D7(IO_8_D7/BOOT_SEL)
N18201976: R241.2 U23.C4(IO_8_C4/NSTATUS/DIFFIO_RX_T24P)
N18202844: R234.2 U23.E5(IO_1B_E5/JTAGEN/DIFFIO_RX_L9P)
N18202890: C233.2 R229.1
N18202989: R243.2 U23.E7(INPUT_ONLY_8_E7/NCONFIG)
N18202999: R242.2 U23.C5(IO_8_C5/CONF_DONE/DIFFIO_RX_T24N)
N18212436: U23.E13(IO_6_E13/CLK3N/DIFFIO_RX_R16N) V8.1(RSNS)
N20449608: CN1.4(ID) R597.1
N20624828: R285.1 R286.2 U31.F7(U0_VSENSEP0)
N20624950: Q27.3(G) R593.1 R594.2
N20624961: Q28.3(G) R595.1 R596.2
N21285306: U32.26(ADCINN) U32.27(MUXOUTN)
N21285312: U32.24(MUXOUTP) U32.25(ADCINP)
N21658191: R5301.1 R5302.2 U31.G12(U1_VSENSEP6)
N22454967: R5392.2 U27.A3(IO_VCC2) U27.A4(IO_VCC1)
N22455559: R5380.1 U27.C4(IO_VL1)
N22455562: R5381.1 U27.C3(IO_VL2)
N22538532: R5384.2 R5386.1 U87.12(VFB)
N22540715: C883.1 R5387.1 U35.3(DXP)
N22540718: C883.2 R5388.1 U35.4(DXN)
N22568920: R5389.1 R5390.1 U88.2(IN_A)

Not connected (* = marked no-connect by the designer): J23 1* 8* 9* 11* 12*; J24 2(TACH)*; SW6 4(A4)* 5(B4)*; SW8 4(A4)* 5(B4)*; U23 B1(IO_1A_B1/DIFFIO_RX_L5P)* B7(IO_8_B7/VREFB8N0)* B9(IO_8_B9/DEV_CLRN/DIFFIO_RX_T16N)* D6(IO_8_D6/CRC_ERROR/DIFFIO_RX_T22N)* D8(IO_8_D8/DEV_OE/DIFFIO_RX_T18P)* D13(IO_6_D13/VREFB6N0)* E1(IO_1A_E1/DIFFIO_RX_L7P)* E6(IO_8_E6/DIFFIO_RX_T22P)* F1(IO_1A_F1/DIFFIO_RX_L7N)* F9(IO_6_F9/DPCLK3/DIFFIO_RX_R26P)* G4(IO_1B_G4/DIFFIO_RX_L14P)* G5(IO_2_G5/CLK0N/DIFFIO_RX_L18N)* H1(IO_1B_H1/VREFB1N0)* H3(IO_1B_H3/DIFFIO_RX_L16P)* H4(IO_2_H4/CLK1P/DIFFIO_RX_L20P)* H5(IO_2_H5/CLK1N/DIFFIO_RX_L20N)* J10(IO_5_J10/DIFFIO_RX_R1N)* K1(IO_2_K1/DIFFIO_RX_L28N)* K2(IO_2_K2/DIFFIO_RX_L28P)* K12(IO_5_K12/DIFFIO_RX_R7P)* K13(IO_5_K13/VREFB5N0)* L1(IO_2_L1/VREFB2N0)* L2(IO_2)* L3(IO_2_L3/PLL_L_CLKOUTP/DIFFIO_RX_L27P)* M3(IO_2_M3/PLL_L_CLKOUTN/DIFFIO_RX_L27N)* M10(IO_3_M10/DIFFIO_TX_RX_B16N)* N2(IO_2_N2/DPCLK0/DIFFIO_RX_L22N)* N11(IO_3_N11/VREFB3N0)* N12(IO_3)*; U24 3(~{MR})*; U26 54(CLKOUT)*; U31 A2(U0_VDD25)* C5(U0_DNC)* E5(U0_VIN_EN)* E7(U0_VDACP0)* E10(U0_VDACP2)* F4(U0_REFM)* F5(U0_REFP)* F10(U0_VDACP1)* G2(U1_VDD25)* G10(U1_VDACP6)* H7(U1_VDACP7)* H10(U1_VDACP5)* J5(U1_DNC)* J7(U1_VOUT_EN7)* L5(U1_VIN_EN)* M3(U1_ASEL0)* M4(U1_REFM)* M5(U1_REFP)*; U32 5(NC)*; U35 5(NC1)* 13(NC2)* 16(NC3)*; U87 1(NC1)* 3(NC2)* 4(NC3)* 5(NC4)* 6(NC5)* 9(NC6)* 10(NC9)* 11(NC8)* 13(NC7)*

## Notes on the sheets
sheet 30
- Max10 USB Blaster II
- FPGA PWR
- Route as matched pair on Top layer
- USB CLK
- SideBus To S10
- USB to MAX V
- JTAG INTERFACE
- PLACE CLOSE CY7C68013
- FMCA Signals
- SW3 Close Logic 0 = Device JTAG Bypass
  SW3 Open Logic 1 = Device JTAG Enable
- To reduce stub, route:
  R5383 shares one pad with R5381
  R5382 shares one pad with R5380
  R5391 shares one pad with R5392
- PLACE CLOSE MAX II PWR PIN
- H = 0.62mm
  Place on Bottom side
sheet 31
- LT2987 Power Sequencer
- 4V
- 4V
- U0 I2C ADDR = 5C (7bit)
- U1 I2C ADDR = 5D (7bit)
- H = 3.62mm
  Place on Top side
- I2C Interface
sheet 32
- Current & Temp Sense
- Current Monitor
- RefVoltage = 0.3V
- I2C Address = b'0010100'
- 3.3V_TSENSE
- Board Temp Sensor
- H = 1.20mm
  Place on bottom side
- I2C ADDR = 4C
- H = 1.73mm
  Place on Bottom side
